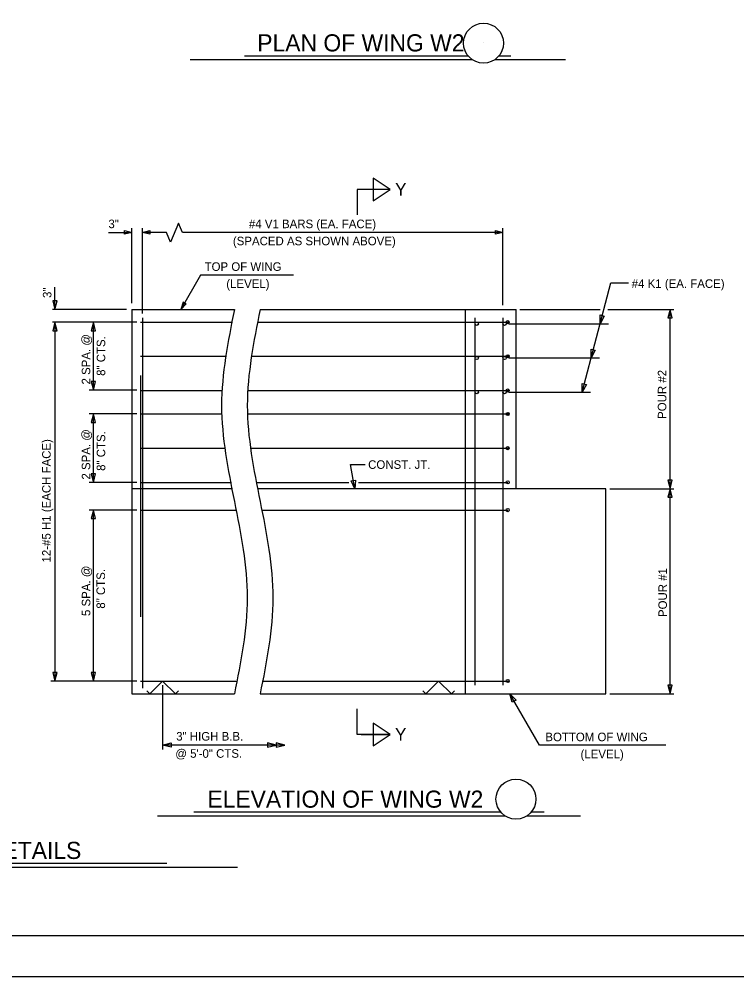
# Model space of a CAD drawing. Extents: x -41 to 251, y -169 to 237.
# Drawn here: x 18.71 to 32.71, y -98.91 to -80.23 of the extents above; entities that cross this region are included whole.
import ezdxf

# ---------------------------------------------------------------- set-up
doc = ezdxf.new("R2010")
doc.units = 0
for name, color, linetype in [('Arrowhead Terminators CELL', 7, 'Continuous'), ('Beam Bolsters CELL', 7, 'Continuous'), ('Default', 7, 'Continuous'), ('Dimension Lines', 7, 'Continuous'), ('Mis Object Lines', 7, 'Continuous'), ('Mis Object Lines Hidden', 7, 'Continuous'), ('Plan Sheet CELL', 7, 'Continuous'), ('Plot Shape CELL', 7, 'Continuous'), ('Rebar K Bar Lines', 7, 'Continuous'), ('Rebar Lines', 7, 'Continuous'), ('Subtitle Text', 7, 'Continuous'), ('Text', 7, 'Continuous'), ('Title Text', 7, 'Continuous'), ('User Information Notes CELL', 7, 'Continuous')]:
    doc.layers.add(name, color=color, linetype=linetype)

# ---------------------------------------------------------------- blocks, each defined once
blk = doc.blocks.new('3 HIGH BEAM BOLSTER')
at = {"layer": 'Default'}
blk.add_lwpolyline([(-0.31, -0.192), (-0.251, -0.251), (0, 0), (0.251, -0.251), (0.31, -0.192)], dxfattribs=at)
blk = doc.blocks.new('SECSYM')
at = {"layer": 'Arrowhead Terminators CELL'}
blk.add_lwpolyline([(0, 0), (-2.48, 1.65), (-2.48, -1.65)], close=True, dxfattribs=at)

msp = doc.modelspace()

# ---------------------------------------------------------------- linework, layer by layer
at = {"layer": 'Arrowhead Terminators CELL'}
for points in [[(20.905, -84.389), (20.763, -84.424), (20.763, -84.353)], [(21.114, -84.389), (21.256, -84.353), (21.256, -84.424)], [(28.142, -84.389), (28, -84.424), (28, -84.353)], [(19.405, -85.889), (19.447, -85.722), (19.364, -85.722)], [(21.862, -85.889), (21.965, -85.784), (21.904, -85.748)], [(31.404, -85.889), (31.362, -86.055), (31.445, -86.055)], [(30.038, -86.17), (30.04, -85.998), (30.121, -86.02)], [(19.405, -86.139), (19.364, -86.305), (19.447, -86.305)], [(20.155, -86.139), (20.114, -86.305), (20.197, -86.305)], [(29.863, -86.837), (29.865, -86.665), (29.946, -86.686)], [(20.155, -87.466), (20.197, -87.299), (20.114, -87.299)], [(29.688, -87.503), (29.69, -87.332), (29.771, -87.353)], [(20.155, -87.93), (20.114, -88.097), (20.197, -88.097)], [(20.155, -89.264), (20.197, -89.097), (20.114, -89.097)], [(25.252, -89.389), (25.183, -89.231), (25.265, -89.218)], [(31.404, -89.389), (31.445, -89.222), (31.362, -89.222)], [(31.404, -89.389), (31.362, -89.555), (31.445, -89.555)], [(20.155, -89.805), (20.114, -89.971), (20.197, -89.971)], [(19.405, -93.139), (19.447, -92.972), (19.364, -92.972)], [(20.155, -93.139), (20.197, -92.972), (20.114, -92.972)], [(31.404, -93.389), (31.445, -93.222), (31.362, -93.222)], [(28.28, -93.389), (28.399, -93.512), (28.327, -93.553)], [(21.505, -94.389), (21.671, -94.347), (21.671, -94.43)], [(23.72, -94.389), (23.554, -94.347), (23.554, -94.43)], [(23.886, -94.389), (23.72, -94.347), (23.72, -94.43)]]:
    msp.add_lwpolyline(points, close=True, dxfattribs=at)
at = {"layer": 'Beam Bolsters CELL'}
msp.add_lwpolyline([(21.814, -93.33), (21.755, -93.389), (21.505, -93.139), (21.254, -93.389), (21.195, -93.33)], dxfattribs=at)
at = {"layer": 'Default'}
msp.add_lwpolyline([(22.024, -84.389), (21.895, -84.389), (21.813, -84.21), (21.659, -84.576), (21.582, -84.389), (21.451, -84.389)], dxfattribs=at)
at = {"layer": 'Dimension Lines'}
for p, q in [((25.302, -83.549), (25.302, -84.048)), ((25.945, -83.549), (25.302, -83.549)), ((20.447, -84.389), (20.905, -84.389)), ((20.905, -85.766), (20.905, -84.305)), ((21.114, -85.972), (21.114, -84.305)), ((21.451, -84.389), (21.114, -84.389)), ((28.142, -84.389), (22.024, -84.389)), ((28.142, -85.805), (28.142, -84.305)), ((29.688, -87.503), (30.247, -85.373)), ((30.247, -85.373), (30.592, -85.373)), ((19.405, -85.889), (19.405, -85.457)), ((20.802, -85.889), (19.357, -85.889)), ((28.476, -85.889), (30.038, -85.889)), ((30.189, -85.889), (31.475, -85.889)), ((31.404, -89.389), (31.404, -85.889)), ((21, -86.139), (19.357, -86.139)), ((19.405, -86.139), (19.405, -93.139)), ((20.155, -87.466), (20.155, -86.139)), ((28.258, -86.17), (30.205, -86.17)), ((28.258, -86.837), (30.03, -86.837)), ((21, -87.466), (20.072, -87.466)), ((28.258, -87.503), (29.855, -87.503)), ((21, -87.93), (20.072, -87.93)), ((20.155, -89.264), (20.155, -87.93)), ((25.252, -89.389), (25.172, -88.912)), ((25.172, -88.912), (25.453, -88.912)), ((21, -89.264), (20.072, -89.264)), ((30.226, -89.389), (31.476, -89.389)), ((31.404, -93.389), (31.404, -89.389)), ((21, -89.805), (20.072, -89.805)), ((20.155, -93.139), (20.155, -89.805)), ((21, -93.139), (19.322, -93.139)), ((21.505, -93.222), (21.505, -94.472)), ((30.226, -93.389), (31.476, -93.389)), ((25.3, -94.181), (25.3, -93.681)), ((25.944, -94.181), (25.3, -94.181)), ((25.379, -94.181), (25.944, -94.181)), ((23.886, -94.389), (21.505, -94.389))]:
    msp.add_line(p, q, dxfattribs=at)
for points in [[(24.055, -85.222), (22.247, -85.222), (21.862, -85.889)], [(31.321, -94.389), (28.858, -94.389), (28.28, -93.389)]]:
    msp.add_lwpolyline(points, dxfattribs=at)
for points in [[(22.905, -85.889), (22.655, -87.764), (22.905, -89.639), (23.155, -91.514), (22.905, -93.389)], [(23.407, -85.889), (23.157, -87.764), (23.407, -89.639), (23.657, -91.514), (23.407, -93.389)]]:
    msp.add_spline(points, degree=3, dxfattribs=at)
at = {"layer": 'Mis Object Lines'}
for p, q in [((20.905, -85.889), (22.905, -85.889)), ((20.905, -85.889), (20.905, -93.389)), ((23.407, -85.889), (28.404, -85.889)), ((28.404, -89.389), (28.404, -85.889)), ((30.154, -89.389), (28.404, -89.389)), ((30.154, -93.389), (30.154, -89.389)), ((20.905, -93.389), (22.905, -93.389)), ((23.407, -93.389), (30.154, -93.389))]:
    msp.add_line(p, q, dxfattribs=at)
at = {"layer": 'Mis Object Lines Hidden'}
for p, q in [((27.404, -85.889), (27.404, -93.389)), ((22.868, -89.389), (20.905, -89.389)), ((28.404, -89.389), (23.37, -89.389))]:
    msp.add_line(p, q, dxfattribs=at)
at = {"layer": 'Plan Sheet CELL'}
msp.add_line((1.402, -98.104), (43.962, -98.104), dxfattribs=at)
at = {"layer": 'Plot Shape CELL'}
msp.add_lwpolyline([(0, -69.65), (43.974, -69.65), (43.974, -98.91), (0, -98.91)], close=True, dxfattribs=at)
at = {"layer": 'Rebar K Bar Lines'}
for centre in [(27.633, -86.17), (28.175, -86.17), (27.633, -86.837), (28.175, -86.837), (27.633, -87.503), (28.175, -87.503)]:
    msp.add_circle(centre, 0.0312, dxfattribs=at)
at = {"layer": 'Rebar Lines'}
for p, q in [((21.112, -86.055), (21.112, -93.276)), ((27.598, -86.055), (27.598, -93.222)), ((28.142, -86.055), (28.142, -93.222)), ((21.072, -86.139), (22.868, -86.139)), ((23.37, -86.139), (28.273, -86.139)), ((21.072, -86.805), (22.752, -86.805)), ((23.254, -86.805), (28.273, -86.805)), ((21.072, -87.472), (22.666, -87.472)), ((23.168, -87.472), (28.273, -87.472)), ((21.072, -87.93), (22.659, -87.93)), ((23.161, -87.93), (28.273, -87.93)), ((21.072, -88.597), (22.732, -88.597)), ((23.234, -88.597), (28.273, -88.597)), ((21.072, -89.264), (22.847, -89.264)), ((23.349, -89.264), (25.135, -89.264)), ((25.324, -89.264), (28.237, -89.264)), ((21.072, -89.805), (22.929, -89.805)), ((23.431, -89.805), (28.237, -89.805)), ((21.072, -93.139), (22.942, -93.139)), ((23.444, -93.139), (28.275, -93.139))]:
    msp.add_line(p, q, dxfattribs=at)
for centre in [(28.237, -86.139), (28.237, -86.805), (28.237, -87.472), (28.237, -87.93), (28.237, -88.597), (28.237, -89.264), (28.237, -89.805), (28.237, -93.139)]:
    msp.add_circle(centre, 0.0312, dxfattribs=at)
at = {"layer": 'Title Text'}
for p, q in [((22.043, -81.015), (27.541, -81.015)), ((23.105, -80.941), (27.462, -80.941)), ((27.989, -81.015), (29.362, -81.015)), ((28.068, -80.941), (28.3, -80.941)), ((21.402, -95.768), (28.183, -95.768)), ((22.114, -95.694), (28.1, -95.694)), ((28.612, -95.768), (29.656, -95.768)), ((28.696, -95.694), (28.945, -95.694)), ((14.226, -96.768), (22.963, -96.768)), ((14.89, -96.768), (21.67, -96.768)), ((15.601, -96.694), (21.587, -96.694))]:
    msp.add_line(p, q, dxfattribs=at)
for centre, radius in [((27.765, -80.696), 0.39), ((27.771, -80.69), 0.000000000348), ((28.398, -95.443), 0.39)]:
    msp.add_circle(centre, radius, dxfattribs=at)
at = {"layer": 'User Information Notes CELL'}
msp.add_line((21.072, -87.179), (21.072, -91.889), dxfattribs=at)

# ---------------------------------------------------------------- block references
at = {"layer": 'Dimension Lines', "xscale": 0.1331292, "yscale": 0.133130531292}
for p in [(25.945, -83.549), (25.944, -94.181)]:
    msp.add_blockref('SECSYM', p, dxfattribs=at)
at = {"layer": 'Rebar Lines', "yscale": 1.00001}
msp.add_blockref('3 HIGH BEAM BOLSTER', (26.889, -93.139), dxfattribs=at)

# ---------------------------------------------------------------- texts
at = {"layer": 'Subtitle Text'}
for p in [(26.04, -83.673), (26.038, -94.305)]:
    msp.add_text('Y', height=0.25, dxfattribs=at).set_placement(p)
at = {"layer": 'Text'}
for s, p in [('3"', (20.447, -84.305)), ('#4 V1 BARS (EA. FACE)', (23.188, -84.305)), ('(SPACED AS SHOWN ABOVE)', (22.876, -84.639)), ('TOP OF WING', (22.324, -85.138)), ('(LEVEL)', (22.747, -85.473)), ('#4 K1 (EA. FACE)', (30.656, -85.47)), ('3" HIGH B.B.', (21.77, -94.301)), ('BOTTOM OF WING', (28.971, -94.313)), ('@ 5\'-0" CTS.', (21.753, -94.636)), ('(LEVEL)', (29.657, -94.648))]:
    msp.add_text(s, height=0.167, dxfattribs=at).set_placement(p)
for s, rotation, p in [('3"', 90, (19.336, -85.667)), ('2 SPA. @', 90, (20.094, -87.354)), ('8" CTS.', 90, (20.386, -87.186)), ('POUR #2', 90, (31.332, -88.026)), ('2 SPA. @', 90, (20.094, -89.209)), ('8" CTS.', 90, (20.386, -89.04)), ('12-#5 H1 (EACH FACE)', 90, (19.322, -90.827)), ('CONST. JT.', 360, (25.514, -89)), ('5 SPA. @', 90, (20.095, -91.871)), ('8" CTS.', 90, (20.382, -91.728)), ('POUR #1', 90, (31.343, -91.891))]:
    msp.add_text(s, height=0.167, rotation=rotation, dxfattribs=at).set_placement(p)
at = {"layer": 'Title Text'}
for s, p in [('PLAN OF WING W2', (23.351, -80.857)), ('ELEVATION OF WING W2', (22.378, -95.61)), ('WING DETAILS', (16.719, -96.61))]:
    msp.add_text(s, height=0.33388, dxfattribs=at).set_placement(p)

doc.saveas('drawing.dxf')
